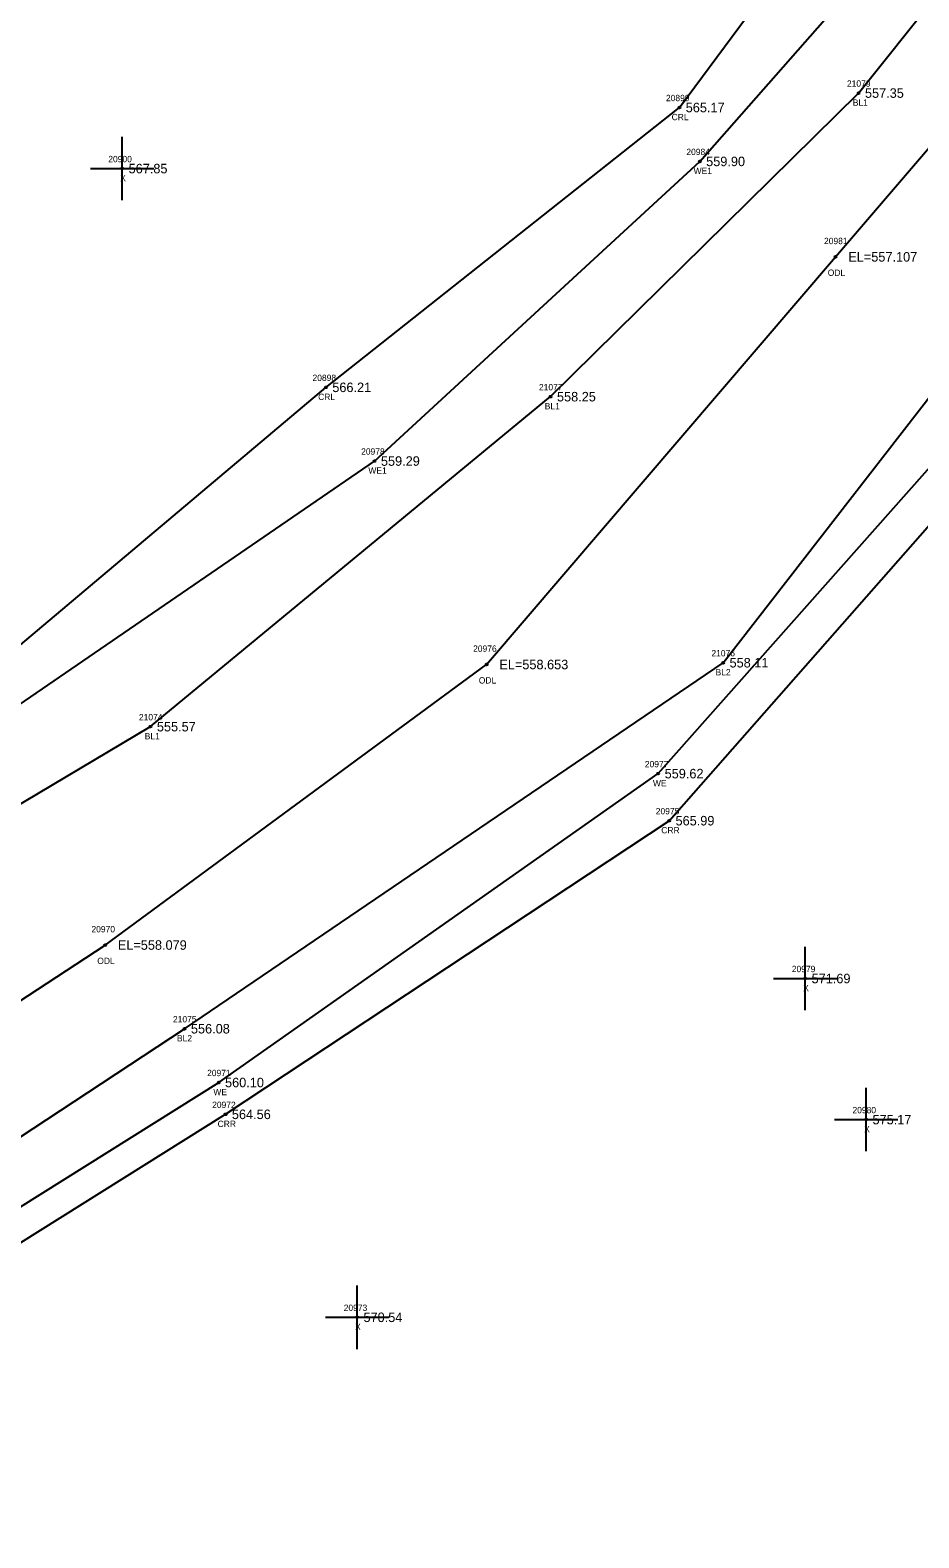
# Model space of a CAD drawing. Extents: x 1695443 to 1696344, y 1087542 to 1090645.
# Drawn here: x 1695596.7 to 1695736.9, y 1088704 to 1088941.8 of the extents above; entities that cross this region are included whole.
import ezdxf

# ---------------------------------------------------------------- set-up
doc = ezdxf.new("R2010")
doc.units = 0
for name, color, linetype in [('RD_DTM_BkLn1', 7, 'Continuous'), ('RD_DTM_BkLn_txCode', 7, 'Continuous'), ('RD_EX_H2O', 7, 'Continuous'), ('RD_EX_H2O_txCode', 7, 'Continuous'), ('RD_EX_Misc', 7, 'Continuous'), ('RD_EX_Misc_txCode', 7, 'Continuous'), ('RD_EX_TX_H2O_ELEV', 7, 'Continuous'), ('RD_EX_TX_Misc_ELEV', 7, 'Continuous'), ('RD_SMD_Locator', 7, 'Continuous')]:
    doc.layers.add(name, color=color, linetype=linetype)

msp = doc.modelspace()

# ---------------------------------------------------------------- linework, layer by layer
at = {"layer": 'RD_DTM_BkLn1'}
for points in [[(1695477.93, 1088750.04), (1695615.7, 1088831.98), (1695678.81, 1088884.02), (1695727.39, 1088931.9), (1695787.9, 1089007.61), (1695838.8, 1089064.32), (1695878.44, 1089095.49), (1695937, 1089135.88), (1696036.12, 1089170.43), (1696157.88, 1089137.18), (1696204, 1089102.76), (1696222.69, 1089094.08), (1696233.22, 1089076.04), (1696249.95, 1089031.73), (1696253.49, 1088951.92)], [(1695519.05, 1088717.19), (1695621.07, 1088784.34), (1695706.03, 1088842.06), (1695754.64, 1088904.72), (1695822.43, 1088986.95), (1695872.19, 1089035.65), (1695897.24, 1089064.09), (1695953.83, 1089097.9), (1696039.66, 1089119.12), (1696131.31, 1089103.56), (1696189.39, 1089073.13), (1696217.04, 1089023.97), (1696212.37, 1088964.66)]]:
    msp.add_lwpolyline(points, dxfattribs=at)
at = {"layer": 'RD_EX_H2O'}
for points in [[(1695466.3, 1088756.42), (1695582.06, 1088826.6), (1695651.04, 1088873.87), (1695702.34, 1088921.12), (1695742.91, 1088967.28), (1695775.02, 1089011.92), (1695840.03, 1089086.93), (1695863.99, 1089105.53), (1695935.01, 1089145.27), (1696036.06, 1089178.39), (1696162.35, 1089145.09), (1696220.48, 1089108.56), (1696243.56, 1089079.86), (1696260.75, 1089035.89), (1696273.81, 1089006.71), (1696286.66, 1088942.65)], [(1695498.69, 1088725.6), (1695608.54, 1088797.54), (1695668.72, 1088841.78), (1695723.76, 1088906.07), (1695797.15, 1088991.78), (1695861.15, 1089050.89), (1695886.72, 1089073.86), (1695948.49, 1089109.39), (1696039, 1089143.17), (1696151.62, 1089114.84), (1696213.01, 1089073.69), (1696220.87, 1089032.47), (1696230.14, 1088992.72), (1696246.9, 1088917.69)], [(1695518.5, 1088708.22), (1695626.45, 1088775.86), (1695695.79, 1088824.57), (1695753.51, 1088889.68), (1695821.81, 1088964.67), (1695880.24, 1089030.4), (1695903.5, 1089050.75), (1695958.92, 1089087.13), (1696042.79, 1089112.69), (1696142.64, 1089092.08), (1696193.08, 1089060.79), (1696207.36, 1089030.79), (1696205.38, 1088967.18), (1696218.5, 1088901.4)], [(1695520.92, 1088704.05), (1695627.53, 1088770.84), (1695697.51, 1088817.15), (1695757.08, 1088884.85), (1695828.4, 1088961.5), (1695887.69, 1089025.09), (1695910.13, 1089043.49), (1695963.83, 1089083.42), (1696041.69, 1089105.91), (1696137.07, 1089082.48), (1696174.24, 1089034.61), (1696185.76, 1089011.54), (1696200.45, 1088973.14), (1696214.06, 1088899.28)], [(1695480.35, 1088771.26), (1695573.72, 1088826.84), (1695643.37, 1088885.49), (1695699.12, 1088929.62), (1695727.71, 1088968.15)]]:
    msp.add_lwpolyline(points, dxfattribs=at)
at = {"layer": 'RD_EX_Misc'}
for p, q in [((1695611.24, 1088914.99), (1695611.24, 1088924.99)), ((1695606.24, 1088919.99), (1695616.24, 1088919.99)), ((1695718.97, 1088787.26), (1695718.97, 1088797.26)), ((1695713.97, 1088792.26), (1695723.97, 1088792.26)), ((1695728.58, 1088765.01), (1695728.58, 1088775.01)), ((1695723.58, 1088770.01), (1695733.58, 1088770.01)), ((1695648.29, 1088733.83), (1695648.29, 1088743.83)), ((1695643.29, 1088738.83), (1695653.29, 1088738.83))]:
    msp.add_line(p, q, dxfattribs=at)
at = {"layer": 'RD_SMD_Locator'}
for centre in [(1695727.39, 1088931.9), (1695699.12, 1088929.62), (1695611.24, 1088919.99), (1695702.34, 1088921.12), (1695723.76, 1088906.07), (1695643.37, 1088885.49), (1695678.81, 1088884.02), (1695651.04, 1088873.87), (1695668.72, 1088841.78), (1695706.03, 1088842.06), (1695615.7, 1088831.98), (1695695.79, 1088824.57), (1695697.51, 1088817.15), (1695608.54, 1088797.54), (1695718.97, 1088792.26), (1695621.07, 1088784.34), (1695626.45, 1088775.86), (1695627.53, 1088770.84), (1695728.58, 1088770.01), (1695648.29, 1088738.83)]:
    msp.add_circle(centre, 0.15, dxfattribs=at)

# ---------------------------------------------------------------- texts
at = {"layer": 'RD_DTM_BkLn_txCode'}
for s, p in [('21079', (1695725.55, 1088932.9)), ('BL1', (1695726.47, 1088929.9)), ('21077', (1695676.97, 1088885.02)), ('BL1', (1695677.88, 1088882.02)), ('21076', (1695704.17, 1088843.06)), ('BL2', (1695704.82, 1088840.06)), ('21074', (1695613.87, 1088832.98)), ('BL1', (1695614.78, 1088829.98)), ('21075', (1695619.24, 1088785.34)), ('BL2', (1695619.87, 1088782.34))]:
    msp.add_text(s, height=1, dxfattribs=at).set_placement(p)
at = {"layer": 'RD_EX_H2O_txCode'}
for s, p in [('20899', (1695697, 1088930.62)), ('CRL', (1695697.89, 1088927.62)), ('20984', (1695700.22, 1088922.12)), ('WE1', (1695701.36, 1088919.12)), ('20981', (1695721.93, 1088908.07)), ('ODL', (1695722.52, 1088903.07)), ('20898', (1695641.25, 1088886.49)), ('CRL', (1695642.14, 1088883.49)), ('20978', (1695648.92, 1088874.87)), ('WE1', (1695650.06, 1088871.87)), ('20976', (1695666.58, 1088843.78)), ('ODL', (1695667.48, 1088838.78)), ('20977', (1695693.67, 1088825.57)), ('WE', (1695694.95, 1088822.57)), ('20975', (1695695.39, 1088818.15)), ('CRR', (1695696.26, 1088815.15)), ('20970', (1695606.38, 1088799.54)), ('ODL', (1695607.3, 1088794.54)), ('20971', (1695624.62, 1088776.86)), ('WE', (1695625.61, 1088773.86)), ('20972', (1695625.42, 1088771.84)), ('CRR', (1695626.28, 1088768.84))]:
    msp.add_text(s, height=1, dxfattribs=at).set_placement(p)
at = {"layer": 'RD_EX_Misc_txCode'}
for s, p in [('20900', (1695609.04, 1088920.99)), ('X', (1695610.92, 1088917.99)), ('20979', (1695716.85, 1088793.26)), ('X', (1695718.65, 1088790.26)), ('20980', (1695726.42, 1088771.01)), ('X', (1695728.27, 1088768.01)), ('20973', (1695646.17, 1088739.83)), ('X', (1695647.97, 1088736.83))]:
    msp.add_text(s, height=1, dxfattribs=at).set_placement(p)
at = {"layer": 'RD_EX_TX_H2O_ELEV'}
for s, p in [('565.17', (1695700.12, 1088928.87)), ('559.90', (1695703.34, 1088920.37)), ('EL=557.107', (1695725.76, 1088905.32)), ('566.21', (1695644.37, 1088884.74)), ('559.29', (1695652.04, 1088873.12)), ('EL=558.653', (1695670.72, 1088841.03)), ('559.62', (1695696.79, 1088823.82)), ('565.99', (1695698.51, 1088816.4)), ('EL=558.079', (1695610.54, 1088796.79)), ('560.10', (1695627.45, 1088775.11)), ('564.56', (1695628.53, 1088770.09))]:
    msp.add_text(s, height=1.5, dxfattribs=at).set_placement(p)
at = {"layer": 'RD_EX_TX_Misc_ELEV'}
for s, p in [('557.35', (1695728.39, 1088931.15)), ('567.85', (1695612.24, 1088919.24)), ('558.25', (1695679.81, 1088883.27)), ('558.11', (1695707.03, 1088841.31)), ('555.57', (1695616.7, 1088831.23)), ('571.69', (1695719.97, 1088791.51)), ('556.08', (1695622.07, 1088783.59)), ('575.17', (1695729.58, 1088769.26)), ('570.54', (1695649.29, 1088738.08))]:
    msp.add_text(s, height=1.5, dxfattribs=at).set_placement(p)

doc.saveas('drawing.dxf')
